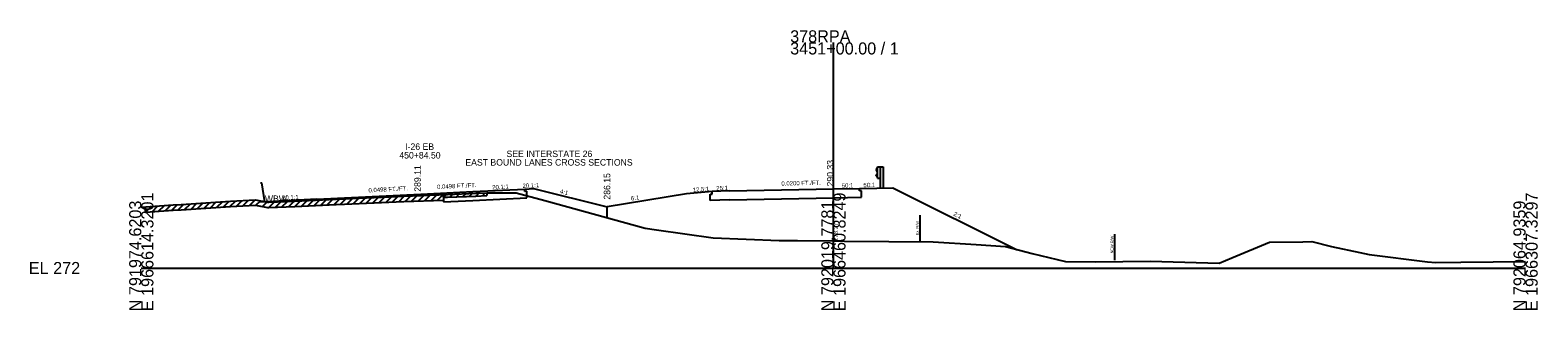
# Model space of a CAD drawing. Extents: x -641 to 3743, y -111 to 9654.
# Drawn here: x 974.3 to 1322.8, y 1490.3 to 1555.1 of the extents above; entities that cross this region are included whole.
import ezdxf

# ---------------------------------------------------------------- set-up
doc = ezdxf.new("R2010")
doc.units = 0
for name, color, linetype in [('BR_CENTER LINES', 7, 'Continuous'), ('RD_DDB_ElevTX', 7, 'Continuous'), ('RD_DDB_GradeTX', 7, 'Continuous'), ('RD_DDB_Profile_EX', 7, 'Continuous'), ('RD_DDB_Profile_Lbl', 7, 'Continuous'), ('RD_DDB_Profile_PR', 7, 'Continuous'), ('RD_DDB_StaTX', 7, 'Continuous'), ('RD_DDB_StripGrade', 7, 'Continuous'), ('RD_DDB_VCLbl', 7, 'Continuous'), ('RD_GPK_Profile_Cell', 7, 'Continuous'), ('RD_HY_PostArea_Clvt2', 7, 'Continuous'), ('RD_HY_PreArea_Clvt4', 7, 'Continuous'), ('RD_HY_TX2', 7, 'Continuous'), ('RD_PD_ALT3_CL', 7, 'Continuous'), ('RD_PD_Final_TX', 7, 'Continuous'), ('RD_PD_SuperShp4', 7, 'Continuous'), ('RD_SHT_TX', 7, 'Continuous'), ('RD_Sketch1', 7, 'Continuous'), ('RD_Sketch2', 7, 'Continuous'), ('RD_Sketch8', 7, 'Continuous'), ('RD_XS_GR', 7, 'Continuous'), ('RD_XS_Pave', 7, 'Continuous'), ('RD_XS_PaveShd', 7, 'Continuous')]:
    doc.layers.add(name, color=color, linetype=linetype)

msp = doc.modelspace()

# ---------------------------------------------------------------- linework, layer by layer
at = {"layer": 'BR_CENTER LINES'}
msp.add_line((1179.97, 1512.21), (1179.97, 1506.21), dxfattribs=at)
at = {"layer": 'RD_DDB_ElevTX'}
for p, q in [((1046.97, 1516.04), (1057.24, 1516.49)), ((1057.24, 1516.49), (1058.89, 1516.56)), ((1058.89, 1516.56), (1060.68, 1516.63)), ((1060.68, 1516.63), (1069.84, 1517)), ((1069.84, 1517), (1069.84, 1515.33)), ((1027.55, 1515.58), (1029.14, 1515.23)), ((1029.14, 1515.23), (1029.48, 1515.25)), ((1029.48, 1515.25), (1035.47, 1515.52)), ((1035.47, 1515.52), (1045.04, 1515.95)), ((1045.04, 1515.95), (1046.97, 1516.04))]:
    msp.add_line(p, q, dxfattribs=at)
at = {"layer": 'RD_DDB_GradeTX'}
for p, q in [((1047.5, 1514.81), (1048.81, 1516.12)), ((1049, 1514.88), (1050.31, 1516.18)), ((1050.5, 1514.94), (1051.81, 1516.25)), ((1052, 1515.01), (1053.31, 1516.31)), ((1053.5, 1515.07), (1054.81, 1516.38)), ((1055, 1515.14), (1056.31, 1516.45)), ((1056.5, 1515.2), (1057.81, 1516.51)), ((1058, 1515.27), (1059.31, 1516.57)), ((1059.5, 1515.33), (1060.8, 1516.63)), ((1061, 1515.39), (1062.3, 1516.7)), ((1062.5, 1515.45), (1063.8, 1516.76)), ((1064, 1515.52), (1065.3, 1516.82)), ((1065.5, 1515.58), (1066.8, 1516.88)), ((1067, 1515.64), (1068.3, 1516.94)), ((1068.5, 1515.7), (1069.8, 1517)), ((1069.84, 1516.38), (1070.49, 1517.03)), ((1071.34, 1516.44), (1071.99, 1517.09)), ((1072.84, 1516.5), (1073.5, 1517.15)), ((1074.35, 1516.56), (1075, 1517.21)), ((1075.85, 1516.62), (1076.5, 1517.27)), ((1077.35, 1516.68), (1078, 1517.33)), ((1078.85, 1516.74), (1079.51, 1517.39)), ((1001, 1512.92), (1002.35, 1514.27)), ((1002.5, 1513.03), (1003.85, 1514.37)), ((1004, 1513.13), (1005.35, 1514.48)), ((1005.5, 1513.24), (1006.85, 1514.58)), ((1007, 1513.35), (1008.35, 1514.69)), ((1008.5, 1513.45), (1009.84, 1514.79)), ((1010, 1513.56), (1011.34, 1514.9)), ((1011.5, 1513.66), (1012.84, 1515)), ((1013, 1513.76), (1014.34, 1515.1)), ((1014.5, 1513.86), (1015.84, 1515.2)), ((1016, 1513.96), (1017.34, 1515.3)), ((1017.5, 1514.06), (1018.84, 1515.4)), ((1019, 1514.16), (1020.34, 1515.5)), ((1020.5, 1514.26), (1021.82, 1515.58)), ((1022, 1514.34), (1023.32, 1515.66)), ((1023.5, 1514.42), (1024.82, 1515.74)), ((1025, 1514.5), (1026.32, 1515.82)), ((1026.5, 1514.56), (1027.53, 1515.58)), ((1028, 1514.23), (1029.03, 1515.26)), ((1029.5, 1514), (1030.81, 1515.31)), ((1031, 1514.07), (1032.31, 1515.38)), ((1032.5, 1514.14), (1033.81, 1515.44)), ((1034, 1514.2), (1035.31, 1515.51)), ((1035.5, 1514.27), (1036.81, 1515.58)), ((1037, 1514.34), (1038.31, 1515.65)), ((1038.5, 1514.4), (1039.81, 1515.71)), ((1040, 1514.47), (1041.31, 1515.78)), ((1041.5, 1514.54), (1042.81, 1515.85)), ((1043, 1514.61), (1044.31, 1515.92)), ((1044.5, 1514.67), (1045.81, 1515.98)), ((1046, 1514.74), (1047.31, 1516.05))]:
    msp.add_line(p, q, dxfattribs=at)
at = {"layer": 'RD_DDB_Profile_Lbl'}
for p, q in [((1069.84, 1517), (1069.84, 1515.75)), ((1069.84, 1516.38), (1069.84, 1517)), ((1069.84, 1516.38), (1070.79, 1516.42)), ((1070.79, 1516.42), (1077.32, 1516.68)), ((1077.32, 1516.68), (1079.86, 1516.78)), ((1079.86, 1517.4), (1079.86, 1516.78)), ((1001, 1512.92), (1001, 1514.17)), ((1001, 1512.92), (1007.34, 1513.37)), ((1007.34, 1513.37), (1009.19, 1513.5)), ((1009.19, 1513.5), (1020.65, 1514.27)), ((1020.65, 1514.27), (1026.41, 1514.58)), ((1026.41, 1514.58), (1029.14, 1513.98)), ((1029.14, 1513.98), (1029.48, 1514)), ((1029.48, 1514), (1035.47, 1514.27)), ((1035.47, 1514.27), (1045.04, 1514.7)), ((1045.04, 1514.7), (1046.97, 1514.79)), ((1046.97, 1514.79), (1057.24, 1515.24)), ((1057.24, 1515.24), (1058.89, 1515.31)), ((1058.89, 1515.31), (1060.68, 1515.38)), ((1060.68, 1515.38), (1069.84, 1515.75))]:
    msp.add_line(p, q, dxfattribs=at)
at = {"layer": 'RD_GPK_Profile_Cell'}
msp.add_lwpolyline([(1000, 1514.1), (1007.34, 1514.62), (1009.19, 1514.75), (1020.65, 1515.52), (1026.41, 1515.83), (1029.14, 1515.23), (1029.48, 1515.25), (1035.47, 1515.52), (1045.04, 1515.95), (1046.97, 1516.04), (1057.24, 1516.49), (1058.89, 1516.56), (1060.68, 1516.63), (1070.79, 1517.04), (1077.32, 1517.3), (1079.86, 1517.4), (1082.53, 1517.42), (1086.68, 1517.41), (1093.25, 1515.67), (1116.48, 1509.21), (1119.13, 1508.86), (1132.2, 1506.98), (1147.47, 1506.38), (1151.69, 1506.38), (1160, 1506.27), (1162.55, 1506.24), (1183.02, 1506.09), (1193.01, 1505.47), (1199.75, 1504.97), (1205.96, 1503.38), (1213.63, 1501.5), (1220.59, 1501.45), (1233.24, 1501.59), (1241.23, 1501.37), (1249.2, 1501.11), (1252.1, 1502.34), (1260.84, 1506), (1268.51, 1506.09), (1270.62, 1506.12), (1275.15, 1504.95), (1281.7, 1503.63), (1283.82, 1503.15), (1297.35, 1501.47), (1299.28, 1501.28), (1305.06, 1501.37), (1320, 1501.54)], dxfattribs=at)
at = {"layer": 'RD_HY_PreArea_Clvt4'}
for p in [(1027.55, 1519.76), (1028.56, 1515.31)]:
    msp.add_line(p, (1027.89, 1519.76), dxfattribs=at)
at = {"layer": 'RD_HY_TX2'}
for p, q in [((1076.62, 1515.66), (1089.14, 1516.29)), ((1088.64, 1517.74), (1088.64, 1518.3)), ((1089.14, 1517.77), (1088.64, 1517.74)), ((1089.14, 1516.29), (1089.14, 1517.77)), ((1131.5, 1517.11), (1132, 1517.13)), ((1131.5, 1515.63), (1131.5, 1517.11)), ((1132, 1517.13), (1132, 1517.69)), ((1136, 1515.81), (1160, 1516.29)), ((1160, 1516.29), (1166.5, 1516.42)), ((1166, 1517.89), (1166, 1518.45)), ((1166.5, 1517.9), (1166, 1517.89)), ((1166.5, 1516.42), (1166.5, 1517.9)), ((1027.55, 1515.26), (1027.55, 1515.58)), ((1069.84, 1515.33), (1076.62, 1515.66)), ((1136, 1515.81), (1131.5, 1515.63))]:
    msp.add_line(p, q, dxfattribs=at)
at = {"layer": 'RD_PD_Final_TX'}
for p, q in [((1088.64, 1518.3), (1090.64, 1518.4)), ((1132, 1517.69), (1126, 1517.21)), ((1166, 1518.45), (1170, 1518.53))]:
    msp.add_line(p, q, dxfattribs=at)
at = {"layer": 'RD_SHT_TX'}
for p, q in [((1076.62, 1517.7), (1088.64, 1518.3)), ((1136, 1517.85), (1132, 1517.69)), ((1160, 1518.33), (1166, 1518.45)), ((1040.57, 1515.91), (1027.55, 1515.26))]:
    msp.add_line(p, q, dxfattribs=at)
at = {"layer": 'RD_Sketch2'}
for p, q in [((1040.57, 1515.91), (1064.61, 1517.11)), ((1064.61, 1517.11), (1076.62, 1517.7)), ((1136, 1517.85), (1160, 1518.33))]:
    msp.add_line(p, q, dxfattribs=at)
at = {"layer": 'RD_Sketch8'}
for p, q in [((1160, 1500), (1160, 1552.25)), ((1000, 1500), (1160, 1500)), ((1160, 1500), (1320, 1500))]:
    msp.add_line(p, q, dxfattribs=at)
at = {"layer": 'RD_XS_GR'}
for p, q in [((1170.15, 1523.24), (1169.88, 1522.8)), ((1170.15, 1523.4), (1170.81, 1523.4)), ((1170.15, 1520.83), (1170.15, 1523.4)), ((1170.81, 1523.4), (1171.48, 1523.4)), ((1170.81, 1523.4), (1170.81, 1518.46)), ((1171.48, 1523.4), (1171.48, 1518.35)), ((1169.88, 1522.8), (1169.88, 1522.69)), ((1169.88, 1522.69), (1170.15, 1522.25)), ((1169.88, 1521.54), (1170.15, 1521.98)), ((1169.88, 1521.43), (1169.88, 1521.54)), ((1170.15, 1520.99), (1169.88, 1521.43)), ((1170.15, 1520.83), (1170.81, 1520.83))]:
    msp.add_line(p, q, dxfattribs=at)
at = {"layer": 'RD_XS_Pave'}
for p, q in [((1090.64, 1518.4), (1107.66, 1514.15)), ((1126, 1517.21), (1107.66, 1514.15)), ((1170, 1518.53), (1173.75, 1518.6)), ((1173.75, 1518.6), (1202.34, 1504.31)), ((1107.66, 1511.67), (1107.66, 1514.15))]:
    msp.add_line(p, q, dxfattribs=at)
at = {"layer": 'RD_XS_PaveShd'}
msp.add_line((1225, 1507.85), (1225, 1501.85), dxfattribs=at)

# ---------------------------------------------------------------- texts
at = {"layer": 'BR_CENTER LINES'}
msp.add_text('Ex. R/W ', height=0.65, rotation=90, dxfattribs=at).set_placement((1179.72, 1507.6))
at = {"layer": 'RD_DDB_Profile_EX'}
msp.add_text('278.27', height=1, rotation=90, dxfattribs=at).set_placement((1161, 1506.27))
at = {"layer": 'RD_DDB_Profile_PR'}
for s, rotation, p in [('0.0498 FT./FT.', 2.851, (1068.39, 1518.29)), ('0.0200 FT./FT.', 1.1458, (1147.98, 1519.09)), ('50:1', 1.1458, (1161.94, 1518.61)), ('0.0498 FT./FT.', 2.8521, (1052.54, 1517.51)), ('4:1', 345.9638, (1096.71, 1517.34)), ('6:1', 9.4623, (1113.26, 1515.59)), ('25:1', 2.2906, (1132.94, 1517.97)), ('2:1', 333.4349, (1187.64, 1512.22))]:
    msp.add_text(s, height=1, rotation=rotation, dxfattribs=at).set_placement(p)
at = {"layer": 'RD_DDB_StaTX'}
for s, p in [('450+84.50', (1059.65, 1525.36)), ('I-26 EB', (1061, 1527.36))]:
    msp.add_text(s, height=1.5, dxfattribs=at).set_placement(p)
at = {"layer": 'RD_DDB_StripGrade'}
msp.add_text('WBW', height=1.5, dxfattribs=at).set_placement((1028.56, 1515.31))
at = {"layer": 'RD_DDB_VCLbl'}
for rotation, p in [(2.8521, (1032.57, 1515.76)), (2.851, (1081.14, 1518.18))]:
    msp.add_text('20.1:1', height=1, rotation=rotation, dxfattribs=at).set_placement(p)
at = {"layer": 'RD_HY_PostArea_Clvt2'}
for s, rotation, p in [('20.1:1', 2.851, (1088.15, 1518.53)), ('50:1', 1.1458, (1166.94, 1518.71)), ('12.5:1', 4.5739, (1127.5, 1517.58))]:
    msp.add_text(s, height=1, rotation=rotation, dxfattribs=at).set_placement(p)
at = {"layer": 'RD_PD_ALT3_CL'}
msp.add_text('286.15', height=1.5, rotation=90, dxfattribs=at).set_placement((1108.41, 1515.84))
at = {"layer": 'RD_PD_SuperShp4'}
for s, p in [('SEE INTERSTATE 26', (1084.42, 1525.69)), ('EAST BOUND LANES CROSS SECTIONS', (1074.91, 1523.72))]:
    msp.add_text(s, height=1.5, dxfattribs=at).set_placement(p)
at = {"layer": 'RD_Sketch1'}
for s, p in [(' 289.11', (1064.61, 1517.11)), (' 290.33', (1160, 1518.33))]:
    msp.add_text(s, height=1.5, rotation=90, dxfattribs=at).set_placement(p)
at = {"layer": 'RD_Sketch8'}
for s, p in [('378RPA', (1150, 1552.25)), ('3451+00.00 / 1', (1150, 1549.45)), ('EL 272', (974, 1498.6))]:
    msp.add_text(s, height=2.8, dxfattribs=at).set_placement(p)
for s, p in [('E 1966614.3201', (1002.8, 1490)), ('E 1966460.8249', (1162.8, 1490)), ('E 1966307.3297', (1322.8, 1490)), ('N 791974.6203', (1000, 1490)), ('N 792019.7781', (1160, 1490)), ('N 792064.9359', (1320, 1490))]:
    msp.add_text(s, height=2.8, rotation=90, dxfattribs=at).set_placement(p)
at = {"layer": 'RD_XS_PaveShd'}
msp.add_text('NEW R/W ', height=0.65, rotation=90, dxfattribs=at).set_placement((1224.73, 1503.4))

doc.saveas('drawing.dxf')
